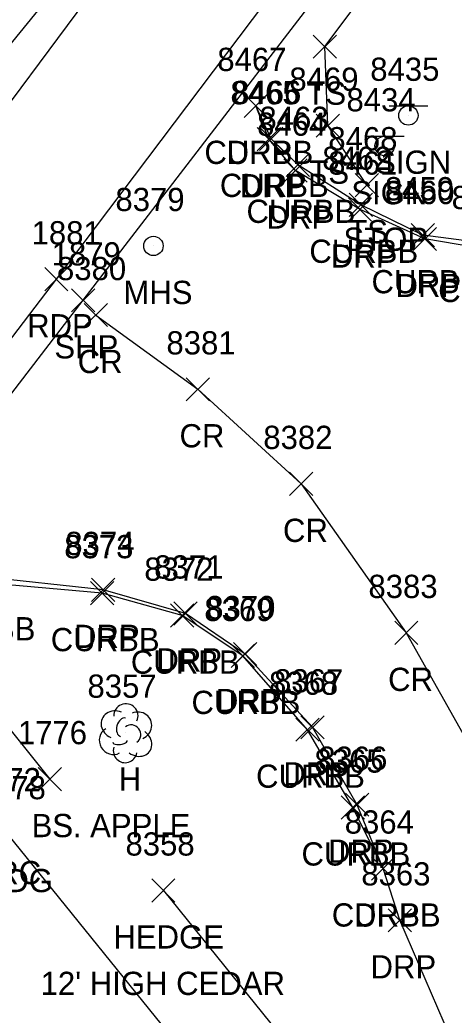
# Model space of a CAD drawing. Extents: x 1769141 to 1770911, y 735471 to 741449.
# Drawn here: x 1770454.7 to 1770492, y 736683.8 to 736769.4 of the extents above; entities that cross this region are included whole.
import ezdxf

# ---------------------------------------------------------------- set-up
doc = ezdxf.new("R2010")
doc.units = 0
for name, color, linetype in [('L_A', 7, 'Continuous'), ('L_C', 7, 'Continuous'), ('L_I', 7, 'Continuous'), ('L_TIC', 7, 'Continuous'), ('LAHR', 7, 'Continuous'), ('LBC', 7, 'Continuous'), ('LELB', 7, 'Continuous'), ('LTD', 7, 'Continuous'), ('P_A', 7, 'Continuous'), ('P_I', 7, 'Continuous'), ('P_TIC', 7, 'Continuous'), ('PET', 7, 'Continuous'), ('PRC', 7, 'Continuous'), ('PSP', 7, 'Continuous'), ('R_A', 7, 'Continuous'), ('R_I', 7, 'Continuous'), ('R_TIC', 7, 'Continuous'), ('RC', 7, 'Continuous'), ('RDP', 7, 'Continuous'), ('S_A', 7, 'Continuous'), ('S_C', 7, 'Continuous'), ('S_I', 7, 'Continuous'), ('SSGN', 7, 'Continuous'), ('U_A', 7, 'Continuous'), ('U_I', 7, 'Continuous'), ('USMH', 7, 'Continuous')]:
    doc.layers.add(name, color=color, linetype=linetype)

msp = doc.modelspace()

# ---------------------------------------------------------------- linework, layer by layer
at = {"layer": 'L_TIC'}
for points in [[(1770479.934, 736766.14), (1770481.934, 736768.14)], [(1770481.934, 736766.14), (1770479.934, 736768.14)], [(1770480.19, 736759.34), (1770482.19, 736761.34)], [(1770482.19, 736759.34), (1770480.19, 736761.34)], [(1770483.533, 736754.214), (1770485.533, 736756.214)], [(1770485.533, 736754.214), (1770483.533, 736756.214)], [(1770456.266, 736703.098), (1770458.266, 736705.098)], [(1770458.266, 736703.098), (1770456.266, 736705.098)], [(1770466.035, 736693.514), (1770468.035, 736695.514)], [(1770468.035, 736693.514), (1770466.035, 736695.514)]]:
    msp.add_lwpolyline(points, dxfattribs=at)
at = {"layer": 'LAHR'}
msp.add_lwpolyline([(1770467.035, 736694.514), (1770486.011, 736671.005), (1770493.865, 736661.467)], dxfattribs=at)
at = {"layer": 'LBC'}
msp.add_lwpolyline([(1770490.666, 736653.543), (1770453.67, 736699.364)], dxfattribs=at)
at = {"layer": 'LELB'}
for points in [[(1770484.533, 736755.214), (1770481.19, 736760.34), (1770480.934, 736767.14), (1770496.87, 736788.433), (1770517.529, 736814.066), (1770527.886, 736827.88), (1770534.718, 736837.012), (1770542.14, 736846.792)], [(1770446.718, 736709.136), (1770450.018, 736713.132), (1770457.266, 736704.098)]]:
    msp.add_lwpolyline(points, dxfattribs=at)
at = {"layer": 'LTD'}
msp.add_line((1770463.765, 736708.098), (1770463.765, 736708.098), dxfattribs=at)
msp.add_line((1770463.765, 736708.098), (1770463.765, 736708.098), dxfattribs=at)
msp.add_arc((1770463.811, 736709.532), 1.047, 335.52715, 180.95627, dxfattribs=at)
for centre, major_axis, ratio, start_param, end_param in [((1770462.973, 736708.765), (1.21, -0.512), 0.895232, 1.570796, 4.712389), ((1770464.806, 736708.682), (-1.141, -0.483), 0.949671, 1.570796, 4.712389), ((1770463.556, 736708.557), (-0.208, -0.792), 0.645439, 3.141593, 6.283185), ((1770462.682, 736707.39), (0.584, -1.042), 0.959034, 3.141593, 6.283185), ((1770464.265, 736707.932), (-0.5, 0.667), 0.989748, 3.141593, 6.283185), ((1770464.765, 736707.265), (-1.09, 0.792), 0.841452, 1.570796, 4.712389), ((1770463.307, 736707.348), (-0.625, -0.083), 0.423636, 0, 3.141593), ((1770463.765, 736706.598), (0.265, 1.061), 0.942809, 1.570796, 4.712389)]:
    msp.add_ellipse(centre, major_axis=major_axis, ratio=ratio, start_param=start_param, end_param=end_param, dxfattribs=at)
at = {"layer": 'P_TIC'}
for points in [[(1770456.829, 736746.118), (1770458.829, 736748.118)], [(1770458.829, 736746.118), (1770456.829, 736748.118)], [(1770459.126, 736744.306), (1770461.126, 736746.306)], [(1770461.126, 736744.306), (1770459.126, 736746.306)], [(1770460.232, 736743.04), (1770462.232, 736745.04)], [(1770462.232, 736743.04), (1770460.232, 736745.04)], [(1770468.992, 736736.647), (1770470.992, 736738.647)], [(1770470.992, 736736.647), (1770468.992, 736738.647)], [(1770477.892, 736728.509), (1770479.892, 736730.509)], [(1770479.892, 736728.509), (1770477.892, 736730.509)], [(1770486.935, 736715.682), (1770488.935, 736717.682)], [(1770488.935, 736715.682), (1770486.935, 736717.682)]]:
    msp.add_lwpolyline(points, dxfattribs=at)
at = {"layer": 'PET'}
msp.add_lwpolyline([(1770275.701, 736500.443), (1770293.456, 736523.994), (1770308.246, 736544.527), (1770339.602, 736585.989), (1770354.041, 736607.647), (1770377.094, 736638.846), (1770405.465, 736677.522), (1770433.078, 736714.634), (1770457.829, 736747.118), (1770487.075, 736785.889), (1770511.852, 736818.72), (1770532.144, 736846.484), (1770557.142, 736879.905), (1770576.719, 736906.621), (1770599.363, 736940.91), (1770615.19, 736970.363), (1770629.485, 737005.853), (1770638.546, 737040.65), (1770643.239, 737068.348), (1770645.294, 737100.928), (1770643.286, 737138.022), (1770637.483, 737178.199), (1770623.12, 737230.101), (1770608.302, 737274.144)], dxfattribs=at)
at = {"layer": 'PRC'}
for points in [[(1770275.213, 736520.725), (1770298.103, 736551.293), (1770321.863, 736584.275), (1770345.264, 736616.165), (1770366.92, 736646.031), (1770396.691, 736686.202), (1770425.295, 736724.734), (1770448.379, 736754.992), (1770477.139, 736793.691), (1770501.731, 736826.243), (1770522.956, 736854.301), (1770547.637, 736887.359), (1770567.264, 736914.203), (1770589.054, 736947.071), (1770604.648, 736975.905), (1770617.455, 737008.215), (1770626.945, 737043.995), (1770631.179, 737069.881), (1770632.95, 737101.223), (1770631.261, 737138.454), (1770625.462, 737176.494), (1770611.429, 737227.28), (1770596.591, 737271.455)], [(1770501.731, 736826.243), (1770471.869, 736789.481), (1770446.573, 736758.432), (1770420.809, 736726.646), (1770393.295, 736692.523), (1770366.574, 736659.288), (1770342, 736628.979), (1770314.016, 736593.334), (1770292.926, 736562.85), (1770274.26, 736537.502)], [(1770461.232, 736744.04), (1770469.992, 736737.647), (1770478.892, 736729.509), (1770487.935, 736716.682), (1770499.748, 736695.671), (1770509.579, 736675.776)]]:
    msp.add_lwpolyline(points, dxfattribs=at)
at = {"layer": 'PSP'}
msp.add_lwpolyline([(1770340.145, 736567.061), (1770355.712, 736595.48), (1770384.336, 736632.07), (1770413.376, 736670.654), (1770426.21, 736690.901), (1770435.181, 736712.82), (1770460.126, 736745.306), (1770489.927, 736784.126), (1770514.631, 736816.065), (1770535.698, 736843.486), (1770560.973, 736877.108), (1770581.175, 736903.184), (1770605.599, 736937.839), (1770621.173, 736966.95), (1770635.97, 737003.978), (1770646.024, 737037.66), (1770650.838, 737066.811), (1770652.594, 737098.802), (1770650.922, 737139.651), (1770647.506, 737164.146), (1770640.683, 737197.771), (1770629.066, 737231.113), (1770614.088, 737275.469)], dxfattribs=at)
at = {"layer": 'R_TIC'}
for points in [[(1770473.983, 736761.042), (1770475.983, 736763.042)], [(1770475.983, 736761.042), (1770473.983, 736763.042)], [(1770473.983, 736761.042), (1770475.983, 736763.042)], [(1770475.983, 736761.042), (1770473.983, 736763.042)], [(1770475.112, 736758.173), (1770477.112, 736760.173)], [(1770477.112, 736758.173), (1770475.112, 736760.173)], [(1770475.312, 736758.2), (1770477.312, 736760.2)], [(1770477.312, 736758.2), (1770475.312, 736760.2)], [(1770477.605, 736755.969), (1770479.605, 736757.969)], [(1770479.605, 736755.969), (1770477.605, 736757.969)], [(1770477.41, 736755.469), (1770479.41, 736757.469)], [(1770479.41, 736755.469), (1770477.41, 736757.469)], [(1770483.013, 736752.53), (1770485.013, 736754.53)], [(1770485.013, 736752.53), (1770483.013, 736754.53)], [(1770482.952, 736752.12), (1770484.952, 736754.12)], [(1770484.952, 736752.12), (1770482.952, 736754.12)], [(1770488.36, 736749.911), (1770490.36, 736751.911)], [(1770490.36, 736749.911), (1770488.36, 736751.911)], [(1770488.52, 736749.585), (1770490.52, 736751.585)], [(1770490.52, 736749.585), (1770488.52, 736751.585)], [(1770460.768, 736719.105), (1770462.768, 736721.105)], [(1770462.768, 736719.105), (1770460.768, 736721.105)], [(1770460.858, 736719.381), (1770462.858, 736721.381)], [(1770462.858, 736719.381), (1770460.858, 736721.381)], [(1770467.946, 736717.356), (1770469.946, 736719.356)], [(1770469.946, 736717.356), (1770467.946, 736719.356)], [(1770467.657, 736717.169), (1770469.657, 736719.169)], [(1770469.657, 736717.169), (1770467.657, 736719.169)], [(1770472.873, 736713.698), (1770474.873, 736715.698)], [(1770474.873, 736713.698), (1770472.873, 736715.698)], [(1770473.068, 736713.862), (1770475.068, 736715.862)], [(1770475.068, 736713.862), (1770473.068, 736715.862)], [(1770478.429, 736707.35), (1770480.429, 736709.35)], [(1770480.429, 736707.35), (1770478.429, 736709.35)], [(1770478.865, 736707.553), (1770480.865, 736709.553)], [(1770480.865, 736707.553), (1770478.865, 736709.553)], [(1770482.334, 736700.655), (1770484.334, 736702.655)], [(1770484.334, 736700.655), (1770482.334, 736702.655)], [(1770482.714, 736700.894), (1770484.714, 736702.894)], [(1770484.714, 736700.894), (1770482.714, 736702.894)], [(1770484.942, 736695.404), (1770486.942, 736697.404)], [(1770486.942, 736695.404), (1770484.942, 736697.404)], [(1770484.942, 736695.404), (1770486.942, 736697.404)], [(1770486.942, 736695.404), (1770484.942, 736697.404)], [(1770486.37, 736690.941), (1770488.37, 736692.941)], [(1770488.37, 736690.941), (1770486.37, 736692.941)]]:
    msp.add_lwpolyline(points, dxfattribs=at)
at = {"layer": 'RC'}
for points in [[(1770504.547, 736752.145), (1770500.091, 736750.768), (1770495.095, 736750.153), (1770489.36, 736750.911), (1770484.013, 736753.53), (1770478.605, 736756.969), (1770476.312, 736759.2), (1770474.983, 736762.042)], [(1770485.942, 736696.404), (1770483.334, 736701.655), (1770479.429, 736708.35), (1770473.873, 736714.698), (1770468.657, 736718.169), (1770461.768, 736720.105), (1770451.084, 736721.036), (1770447.846, 736721.127)]]:
    msp.add_lwpolyline(points, dxfattribs=at)
at = {"layer": 'RDP'}
for points in [[(1770583.523, 736784.378), (1770574.054, 736786.974), (1770566.114, 736788.183), (1770553.543, 736787.147), (1770540.72, 736782.788), (1770531.403, 736777.675), (1770523.515, 736770.525), (1770510.016, 736756.718), (1770504.547, 736752.145), (1770500.245, 736750.373), (1770495.258, 736749.629), (1770489.52, 736750.585), (1770483.952, 736753.12), (1770478.41, 736756.469), (1770476.112, 736759.173), (1770474.983, 736762.042)], [(1770500.819, 736664.66), (1770493.909, 736676.805), (1770487.37, 736691.941), (1770485.942, 736696.404), (1770483.714, 736701.894), (1770479.865, 736708.553), (1770474.068, 736714.862), (1770468.946, 736718.356), (1770461.858, 736720.381), (1770451.262, 736721.528), (1770447.846, 736721.127), (1770444.17, 736720.647)]]:
    msp.add_lwpolyline(points, dxfattribs=at)
at = {"layer": 'SSGN'}
for p, q in [((1770486.464, 736762.048), (1770489.797, 736762.048)), ((1770488.111, 736761.215), (1770488.111, 736761.215)), ((1770484.418, 736759.422), (1770487.752, 736759.422)), ((1770486.065, 736758.588), (1770486.065, 736758.588))]:
    msp.add_line(p, q, dxfattribs=at)
for centre in [(1770488.111, 736761.215), (1770486.065, 736758.588)]:
    msp.add_circle(centre, 0.833, dxfattribs=at)
at = {"layer": 'USMH'}
for p, q in [((1770466.18, 736749.986), (1770466.18, 736749.986)), ((1770467.013, 736749.986), (1770467.013, 736749.986))]:
    msp.add_line(p, q, dxfattribs=at)
msp.add_circle((1770466.18, 736749.986), 0.833, dxfattribs=at)

# ---------------------------------------------------------------- texts
at = {"layer": 'L_A'}
for s, p in [('TS', (1770479.343, 736762.14)), ('TS', (1770479.599, 736755.34)), ('TS', (1770482.942, 736750.214)), ('H', (1770463.198, 736703.098)), ('BS', (1770455.707, 736699.098)), ('BLDG', (1770450.26, 736694.364)), ('HEDGE', (1770462.736, 736689.514))]:
    msp.add_text(s, height=2, dxfattribs=at).set_placement(p)
at = {"layer": 'L_C'}
for s, p in [('S. APPLE', (1770457.466, 736699.098)), ("12' HIGH CEDAR", (1770456.476, 736685.514))]:
    msp.add_text(s, height=2, dxfattribs=at).set_placement(p)
at = {"layer": 'L_I'}
for s, p in [('8469', (1770477.875, 736763.34)), ('8468', (1770481.225, 736758.214)), ('8357', (1770460.505, 736711.098)), ('1776', (1770454.518, 736707.098)), ('1878', (1770450.977, 736702.364)), ('8358', (1770463.775, 736697.514))]:
    msp.add_text(s, height=2, dxfattribs=at).set_placement(p)
at = {"layer": 'P_A'}
for s, p in [('RDP', (1770455.317, 736742.118)), ('SHP', (1770457.662, 736740.306)), ('CR', (1770459.665, 736739.04)), ('CR', (1770468.425, 736732.647)), ('CR', (1770477.325, 736724.509)), ('CR', (1770486.368, 736711.682))]:
    msp.add_text(s, height=2, dxfattribs=at).set_placement(p)
at = {"layer": 'P_I'}
for s, p in [('1881', (1770455.703, 736750.118)), ('1879', (1770457.425, 736748.306)), ('8380', (1770457.885, 736747.04)), ('8381', (1770467.299, 736740.647)), ('8382', (1770475.632, 736732.509)), ('8383', (1770484.675, 736719.682))]:
    msp.add_text(s, height=2, dxfattribs=at).set_placement(p)
at = {"layer": 'R_A'}
for s, p in [('CURBB', (1770470.566, 736757.042)), ('DRP', (1770472.471, 736757.042)), ('CURBB', (1770471.895, 736754.2)), ('DRP', (1770473.6, 736754.173)), ('CURBB', (1770474.187, 736751.969)), ('DRP', (1770475.898, 736751.469)), ('CURBB', (1770479.595, 736748.53)), ('DRP', (1770481.44, 736748.12)), ('CURBB', (1770484.943, 736745.911)), ('DRP', (1770487.008, 736745.585)), ('CURBB', (1770490.677, 736745.153)), ('CURBB', (1770446.667, 736716.036)), ('CURBB', (1770457.351, 736715.105)), ('DRP', (1770459.347, 736715.381)), ('CURBB', (1770464.239, 736713.169)), ('DRP', (1770466.435, 736713.356)), ('CURBB', (1770469.456, 736709.698)), ('DRP', (1770471.556, 736709.862)), ('CURBB', (1770475.011, 736703.35)), ('DRP', (1770477.353, 736703.553)), ('DRP', (1770481.202, 736696.894)), ('CURBB', (1770478.917, 736696.655)), ('DRC', (1770450.728, 736695.049)), ('CURBB', (1770481.525, 736691.404)), ('DRP', (1770483.43, 736691.404)), ('DRP', (1770484.859, 736686.941))]:
    msp.add_text(s, height=2, dxfattribs=at).set_placement(p)
at = {"layer": 'R_I'}
for s, p in [('8467', (1770471.676, 736765.042)), ('8467', (1770471.676, 736765.042)), ('8465', (1770472.805, 736762.173)), ('8466', (1770472.95, 736762.2)), ('8464', (1770475.102, 736759.469)), ('8463', (1770475.298, 736759.969)), ('8462', (1770480.706, 736756.53)), ('8461', (1770481.212, 736756.12)), ('8459', (1770486.092, 736753.911)), ('8460', (1770486.126, 736753.585)), ('8458', (1770491.835, 736753.153)), ('8374', (1770458.598, 736723.381)), ('8373', (1770458.508, 736723.105)), ('8372', (1770465.397, 736721.169)), ('8371', (1770466.253, 736721.356)), ('8369', (1770470.558, 736717.698)), ('8370', (1770470.722, 736717.862)), ('8368', (1770476.121, 736711.35)), ('8367', (1770476.558, 736711.553)), ('8365', (1770480.027, 736704.655)), ('8366', (1770480.352, 736704.894)), ('1772', (1770450.547, 736703.049)), ('8364', (1770482.635, 736699.404)), ('8364', (1770482.635, 736699.404)), ('8363', (1770484.063, 736694.941))]:
    msp.add_text(s, height=2, dxfattribs=at).set_placement(p)
at = {"layer": 'S_A'}
for p in [(1770485.249, 736756.195), (1770483.203, 736753.568)]:
    msp.add_text('SIGN', height=2, dxfattribs=at).set_placement(p)
at = {"layer": 'S_C'}
msp.add_text('STOP', height=2, dxfattribs=at).set_placement((1770482.526, 736749.568))
at = {"layer": 'S_I'}
for s, p in [('8435', (1770484.831, 736764.195)), ('8434', (1770482.786, 736761.568))]:
    msp.add_text(s, height=2, dxfattribs=at).set_placement(p)
at = {"layer": 'U_A'}
msp.add_text('MHS', height=2, dxfattribs=at).set_placement((1770463.597, 736744.986))
at = {"layer": 'U_I'}
msp.add_text('8379', height=2, dxfattribs=at).set_placement((1770462.912, 736752.986))

doc.saveas('drawing.dxf')
